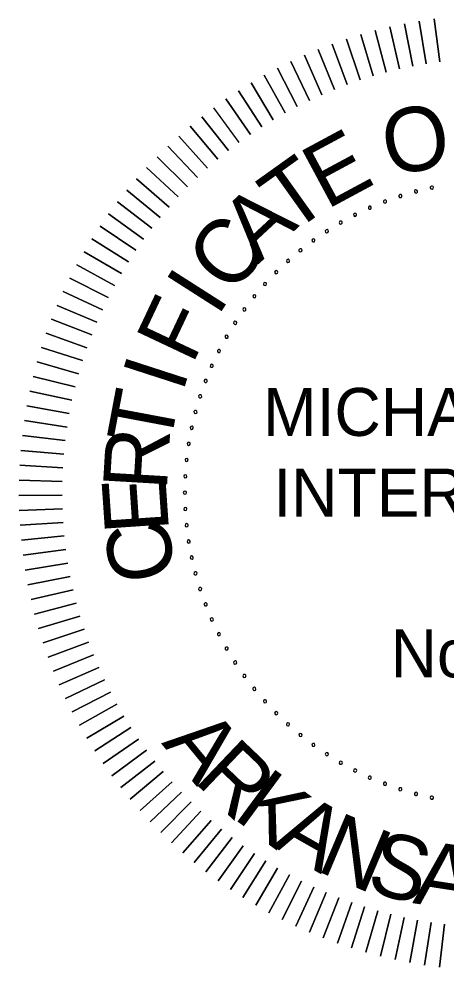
# Model space of a CAD drawing. Extents: x 166 to 3995, y -61 to 2074.
# Drawn here: x 3477.6 to 3588.9, y 251.2 to 498.1 of the extents above; entities that cross this region are included whole.
import ezdxf

# ---------------------------------------------------------------- set-up
doc = ezdxf.new("R2010")
doc.units = 0
doc.layers.add('G-ANNO-TEXT', color=7, linetype='Continuous')

msp = doc.modelspace()

# ---------------------------------------------------------------- linework, layer by layer
at = {"layer": 'G-ANNO-TEXT'}
for points in [[(3580.23, 485.84), (3578.07, 496.85)], [(3578.07, 496.85), (3580.23, 485.84)], [(3583.73, 486.47), (3581.92, 497.54)], [(3581.92, 497.54), (3583.73, 486.47)], [(3587.25, 486.99), (3585.78, 498.12)], [(3585.78, 498.12), (3587.25, 486.99)], [(3569.88, 483.29), (3566.68, 494.05)], [(3566.68, 494.05), (3569.88, 483.29)], [(3573.3, 484.25), (3570.45, 495.1)], [(3570.45, 495.1), (3573.3, 484.25)], [(3576.75, 485.1), (3574.25, 496.04)], [(3574.25, 496.04), (3576.75, 485.1)], [(3563.12, 481.06), (3559.26, 491.59)], [(3559.26, 491.59), (3563.12, 481.06)], [(3566.48, 482.23), (3562.95, 492.88)], [(3562.95, 492.88), (3566.48, 482.23)], [(3559.8, 479.78), (3555.61, 490.19)], [(3555.61, 490.19), (3559.8, 479.78)], [(3553.29, 476.92), (3548.46, 487.05)], [(3548.46, 487.05), (3553.29, 476.92)], [(3556.53, 478.4), (3552.01, 488.68)], [(3552.01, 488.68), (3556.53, 478.4)], [(3550.11, 475.34), (3544.96, 485.31)], [(3544.96, 485.31), (3550.11, 475.34)], [(3543.89, 471.88), (3538.13, 481.5)], [(3538.13, 481.5), (3543.89, 471.88)], [(3546.97, 473.65), (3541.51, 483.46)], [(3541.51, 483.46), (3546.97, 473.65)], [(3540.87, 470), (3534.8, 479.44)], [(3534.8, 479.44), (3540.87, 470)], [(3537.91, 468.03), (3531.55, 477.28)], [(3531.55, 477.28), (3537.91, 468.03)], [(3535.01, 465.97), (3528.36, 475.01)], [(3532.18, 463.82), (3525.25, 472.65)], [(3525.25, 472.65), (3532.18, 463.82)], [(3529.41, 461.58), (3522.21, 470.19)], [(3522.21, 470.19), (3529.41, 461.58)], [(3526.72, 459.25), (3519.25, 467.63)], [(3519.25, 467.63), (3526.72, 459.25)], [(3524.11, 456.85), (3516.38, 464.98)], [(3516.38, 464.98), (3524.11, 456.85)], [(3521.57, 454.36), (3513.59, 462.25)], [(3513.59, 462.25), (3521.57, 454.36)], [(3519.1, 451.79), (3510.88, 459.42)], [(3510.88, 459.42), (3519.1, 451.79)], [(3516.73, 449.14), (3508.27, 456.52)], [(3508.27, 456.52), (3516.73, 449.14)], [(3514.43, 446.43), (3505.74, 453.53)], [(3505.74, 453.53), (3514.43, 446.43)], [(3512.22, 443.64), (3503.32, 450.47)], [(3503.32, 450.47), (3512.22, 443.64)], [(3510.1, 440.78), (3500.99, 447.33)], [(3500.99, 447.33), (3510.1, 440.78)], [(3508.07, 437.86), (3498.76, 444.12)], [(3498.76, 444.12), (3508.07, 437.86)], [(3506.14, 434.88), (3496.63, 440.84)], [(3496.63, 440.84), (3506.14, 434.88)], [(3504.3, 431.83), (3494.6, 437.49)], [(3494.6, 437.49), (3504.3, 431.83)], [(3502.55, 428.74), (3492.69, 434.09)], [(3492.69, 434.09), (3502.55, 428.74)], [(3500.9, 425.58), (3490.88, 430.62)], [(3490.88, 430.62), (3500.9, 425.58)], [(3499.36, 422.38), (3489.18, 427.1)], [(3489.18, 427.1), (3499.36, 422.38)], [(3497.91, 419.13), (3487.59, 423.53)], [(3487.59, 423.53), (3497.91, 419.13)], [(3496.57, 415.84), (3486.11, 419.91)], [(3486.11, 419.91), (3496.57, 415.84)], [(3495.33, 412.5), (3484.75, 416.25)], [(3484.75, 416.25), (3495.33, 412.5)], [(3494.2, 409.13), (3483.5, 412.54)], [(3483.5, 412.54), (3494.2, 409.13)], [(3493.17, 405.73), (3482.38, 408.8)], [(3482.38, 408.8), (3493.17, 405.73)], [(3492.25, 402.29), (3481.37, 405.02)], [(3481.37, 405.02), (3492.25, 402.29)], [(3491.44, 398.83), (3480.47, 401.21)], [(3480.47, 401.21), (3491.44, 398.83)], [(3490.74, 395.34), (3479.7, 397.38)], [(3479.7, 397.38), (3490.74, 395.34)], [(3490.15, 391.83), (3479.05, 393.53)], [(3479.05, 393.53), (3490.15, 391.83)], [(3489.66, 388.31), (3478.52, 389.65)], [(3478.52, 389.65), (3489.66, 388.31)], [(3489.29, 384.77), (3478.12, 385.77)], [(3478.12, 385.77), (3489.29, 384.77)], [(3489.03, 381.22), (3477.83, 381.87)], [(3477.83, 381.87), (3489.03, 381.22)], [(3488.89, 377.67), (3477.67, 377.96)], [(3477.67, 377.96), (3488.89, 377.67)], [(3488.85, 374.11), (3477.63, 374.05)], [(3477.63, 374.05), (3488.85, 374.11)], [(3488.93, 370.56), (3477.71, 370.14)], [(3477.71, 370.14), (3488.93, 370.56)], [(3489.11, 367.01), (3477.92, 366.24)], [(3477.92, 366.24), (3489.11, 367.01)], [(3489.41, 363.46), (3478.25, 362.34)], [(3478.25, 362.34), (3489.41, 363.46)], [(3489.82, 359.93), (3478.7, 358.46)], [(3478.7, 358.46), (3489.82, 359.93)], [(3490.34, 356.41), (3479.27, 354.59)], [(3479.27, 354.59), (3490.34, 356.41)], [(3490.97, 352.91), (3479.96, 350.75)], [(3479.96, 350.75), (3490.97, 352.91)], [(3491.72, 349.43), (3480.78, 346.92)], [(3480.78, 346.92), (3491.72, 349.43)], [(3492.56, 345.98), (3481.71, 343.13)], [(3481.71, 343.13), (3492.56, 345.98)], [(3493.52, 342.55), (3482.76, 339.36)], [(3482.76, 339.36), (3493.52, 342.55)], [(3494.59, 339.16), (3483.93, 335.63)], [(3483.93, 335.63), (3494.59, 339.16)], [(3495.76, 335.8), (3485.22, 331.94)], [(3485.22, 331.94), (3495.76, 335.8)], [(3497.03, 332.48), (3486.62, 328.29)], [(3486.62, 328.29), (3497.03, 332.48)], [(3498.41, 329.2), (3488.14, 324.69)], [(3488.14, 324.69), (3498.41, 329.2)], [(3499.89, 325.97), (3489.77, 321.13)], [(3489.77, 321.13), (3499.89, 325.97)], [(3501.48, 322.78), (3491.51, 317.63)], [(3491.51, 317.63), (3501.48, 322.78)], [(3503.16, 319.65), (3493.36, 314.19)], [(3493.36, 314.19), (3503.16, 319.65)], [(3504.94, 316.57), (3495.31, 310.8)], [(3495.31, 310.8), (3504.94, 316.57)], [(3506.81, 313.55), (3497.37, 307.48)], [(3497.37, 307.48), (3506.81, 313.55)], [(3508.78, 310.59), (3499.54, 304.23)], [(3499.54, 304.23), (3508.78, 310.59)], [(3510.84, 307.69), (3501.8, 301.04)], [(3501.8, 301.04), (3510.84, 307.69)], [(3513, 304.86), (3504.17, 297.93)], [(3504.17, 297.93), (3513, 304.86)], [(3515.23, 302.09), (3506.63, 294.89)], [(3506.63, 294.89), (3515.23, 302.09)], [(3517.56, 299.4), (3509.18, 291.93)], [(3509.18, 291.93), (3517.56, 299.4)], [(3519.97, 296.78), (3511.83, 289.06)], [(3511.83, 289.06), (3519.97, 296.78)], [(3522.46, 294.24), (3514.57, 286.26)], [(3514.57, 286.26), (3522.46, 294.24)], [(3525.03, 291.78), (3517.39, 283.56)], [(3517.39, 283.56), (3525.03, 291.78)], [(3520.29, 280.94), (3527.67, 289.4)], [(3527.67, 289.4), (3520.29, 280.94)], [(3523.28, 278.42), (3530.39, 287.11)], [(3530.39, 287.11), (3523.28, 278.42)], [(3526.35, 275.99), (3533.18, 284.9)], [(3533.18, 284.9), (3526.35, 275.99)], [(3529.49, 273.66), (3536.03, 282.78)], [(3536.03, 282.78), (3529.49, 273.66)], [(3532.7, 271.43), (3538.95, 280.75)], [(3538.95, 280.75), (3532.7, 271.43)], [(3535.98, 269.31), (3541.94, 278.82)], [(3541.94, 278.82), (3535.98, 269.31)], [(3539.32, 267.28), (3544.98, 276.97)], [(3544.98, 276.97), (3539.32, 267.28)], [(3542.73, 265.36), (3548.08, 275.23)], [(3548.08, 275.23), (3542.73, 265.36)], [(3546.19, 263.55), (3551.23, 273.58)], [(3551.23, 273.58), (3546.19, 263.55)], [(3549.71, 261.85), (3554.43, 272.04)], [(3554.43, 272.04), (3549.71, 261.85)], [(3553.28, 260.27), (3557.68, 270.59)], [(3557.68, 270.59), (3553.28, 260.27)], [(3556.9, 258.79), (3560.98, 269.25)], [(3560.98, 269.25), (3556.9, 258.79)], [(3560.57, 257.43), (3564.31, 268.01)], [(3564.31, 268.01), (3560.57, 257.43)], [(3564.27, 256.18), (3567.68, 266.88)], [(3567.68, 266.88), (3564.27, 256.18)], [(3568.02, 255.05), (3571.09, 265.85)], [(3571.09, 265.85), (3568.02, 255.05)], [(3571.79, 254.04), (3574.52, 264.93)], [(3574.52, 264.93), (3571.79, 254.04)], [(3575.6, 253.15), (3577.99, 264.12)], [(3577.99, 264.12), (3575.6, 253.15)], [(3579.43, 252.38), (3581.47, 263.42)], [(3581.47, 263.42), (3579.43, 252.38)], [(3583.29, 251.73), (3584.98, 262.82)], [(3584.98, 262.82), (3583.29, 251.73)], [(3587.16, 251.2), (3588.5, 262.34)], [(3588.5, 262.34), (3587.16, 251.2)]]:
    msp.add_lwpolyline(points, dxfattribs=at)
for centre, start, end in [((3585.18, 454.19), 12, 192), ((3576.97, 451.99), 18, 198), ((3576.97, 451.99), 198, 18), ((3581.05, 453.19), 15, 195), ((3581.05, 453.19), 195, 15), ((3585.18, 454.19), 192, 12), ((3572.96, 450.57), 21, 201), ((3572.96, 450.57), 201, 21), ((3565.2, 447.11), 27, 207), ((3565.2, 447.11), 207, 27), ((3569.03, 448.94), 24, 204), ((3569.03, 448.94), 204, 24), ((3561.46, 445.08), 30, 210), ((3561.46, 445.08), 210, 30), ((3557.84, 442.86), 33, 213), ((3557.84, 442.86), 213, 33), ((3554.33, 440.45), 36, 216), ((3554.33, 440.45), 216, 36), ((3550.96, 437.86), 39, 219), ((3550.96, 437.86), 219, 39), ((3547.72, 435.1), 42, 222), ((3547.72, 435.1), 222, 42), ((3544.64, 432.17), 45, 225), ((3544.64, 432.17), 225, 45), ((3541.71, 429.09), 48, 228), ((3541.71, 429.09), 228, 48), ((3538.95, 425.86), 51, 231), ((3538.95, 425.86), 231, 51), ((3536.36, 422.48), 54, 234), ((3536.36, 422.48), 234, 54), ((3533.96, 418.98), 57, 237), ((3533.96, 418.98), 237, 57), ((3531.73, 415.35), 60, 240), ((3531.73, 415.35), 240, 60), ((3529.71, 411.62), 63, 243), ((3529.71, 411.62), 243, 63), ((3527.87, 407.78), 66, 246), ((3527.87, 407.78), 246, 66), ((3526.25, 403.85), 69, 249), ((3526.25, 403.85), 249, 69), ((3524.83, 399.84), 72, 252), ((3524.83, 399.84), 252, 72), ((3523.62, 395.77), 75, 255), ((3523.62, 395.77), 255, 75), ((3522.63, 391.63), 78, 258), ((3522.63, 391.63), 258, 78), ((3521.85, 387.45), 81, 261), ((3521.85, 387.45), 261, 81), ((3521.3, 383.24), 84, 264), ((3521.3, 383.24), 264, 84), ((3520.96, 379), 87, 267), ((3520.96, 379), 267, 87), ((3520.85, 374.75), 90, 270), ((3520.85, 374.75), 270, 90), ((3520.96, 370.5), 93, 273), ((3520.96, 370.5), 273, 93), ((3521.3, 366.26), 96, 276), ((3521.3, 366.26), 276, 96), ((3521.85, 362.04), 99, 279), ((3521.85, 362.04), 279, 99), ((3522.63, 357.86), 102, 282), ((3522.63, 357.86), 282, 102), ((3523.62, 353.73), 105, 285), ((3523.62, 353.73), 285, 105), ((3524.83, 349.65), 108, 288), ((3524.83, 349.65), 288, 108), ((3526.25, 345.64), 111, 291), ((3526.25, 345.64), 291, 111), ((3527.87, 341.71), 114, 294), ((3527.87, 341.71), 294, 114), ((3529.71, 337.88), 297, 117), ((3529.71, 337.88), 117, 297), ((3531.73, 334.14), 120, 300), ((3531.73, 334.14), 300, 120), ((3533.96, 330.51), 303, 123), ((3533.96, 330.51), 123, 303), ((3536.36, 327.01), 126, 306), ((3536.36, 327.01), 306, 126), ((3538.95, 323.64), 129, 309), ((3538.95, 323.64), 309, 129), ((3541.71, 320.4), 132, 312), ((3541.71, 320.4), 312, 132), ((3544.64, 317.32), 135, 315), ((3544.64, 317.32), 315, 135), ((3547.72, 314.39), 138, 318), ((3547.72, 314.39), 318, 138), ((3550.96, 311.63), 141, 321), ((3550.96, 311.63), 321, 141), ((3554.33, 309.04), 144, 324), ((3554.33, 309.04), 324, 144), ((3557.84, 306.63), 147, 327), ((3557.84, 306.63), 327, 147), ((3561.46, 304.41), 150, 330), ((3561.46, 304.41), 330, 150), ((3565.2, 302.38), 153, 333), ((3565.2, 302.38), 333, 153), ((3569.03, 300.55), 156, 336), ((3569.03, 300.55), 336, 156), ((3572.96, 298.93), 159, 339), ((3572.96, 298.93), 339, 159), ((3576.97, 297.51), 162, 342), ((3576.97, 297.51), 342, 162), ((3581.05, 296.3), 165, 345), ((3581.05, 296.3), 345, 165), ((3585.18, 295.31), 348, 168), ((3585.18, 295.31), 168, 348)]:
    msp.add_arc(centre, 0.417, start, end, dxfattribs=at)

# ---------------------------------------------------------------- texts
for s, rotation, p in [('O', 10.7295, (3573.91, 457.07)), ('E', 28.279, (3557.72, 448.34)), ('T', 35.5725, (3548.42, 441.89)), ('A', 42.8659, (3539.96, 434.18)), ('C', 50.1594, (3532.94, 425.85)), ('I', 57.4529, (3529.32, 420.28)), ('F', 64.7464, (3522.78, 407.82)), ('I', 72.0398, (3520.2, 400.49)), ('T', 79.3333, (3516.88, 386.13)), ('R', 86.6268, (3516.12, 375.11)), ('E', 93.9203, (3516.74, 364.7)), ('C', 101.2137, (3518.87, 353.11)), ('A', 309.5859, (3514.6, 309.48)), ('R', 316.3356, (3522.88, 299.65)), ('K', 323.6428, (3533.07, 290.19)), ('A', 330.3925, (3543.49, 282.67)), ('N', 337.1422, (3554.72, 276.42)), ('S', 344.4494, (3567.61, 271.2)), ('A', 351.1991, (3580.02, 267.87))]:
    msp.add_text(s, height=16.67, rotation=rotation, dxfattribs=at).set_placement(p)
for s, height, p in [('MICHAEL BAKER', 12.5016, (3541.24, 389.52)), (' INTERNATIONAL', 12.5016, (3539.23, 368.5)), (' No. 1126', 12.502, (3569.8, 326.64))]:
    msp.add_text(s, height=height, dxfattribs=at).set_placement(p)

doc.saveas('drawing.dxf')
